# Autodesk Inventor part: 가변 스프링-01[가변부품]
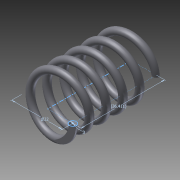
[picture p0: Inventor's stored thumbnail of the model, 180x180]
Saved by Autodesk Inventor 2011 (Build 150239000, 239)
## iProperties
Created: 2015-05
Part Number: 가변 스프링-01[가변부품]
Document SubType Name: Modeling
Designer: Administrator
Density: 7.87 g/cm^3
Mass: 18.9242 g
Surface Area: 32.5548 cm^2
Volume: 2.40459 cm^3
Material: 탄소강
Author: Administrator
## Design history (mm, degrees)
sketch "스케치1"
  geometry: L1 (0, 0)-(11, 0); L2 (11, 0)-(11, 36.411); L3 (11, 36.411)-(0, 36.411); L4 (0, 36.411)-(0, 0); C1 r 1.5 at (11, 0)
  constraints: 8 end point, 2 parallel, 1 centre point, 1 coincident, 1 horizontal, 1 perpendicular
  dimensions: "d0" = 22 diameter of L2 L4; "d1" = 3 diameter of C1; "d2" = 36.4112 distance of L1.end L2.end (derived)
feature "코일1" pitch "d3" = 10; turns "d5" = 5; dims "d4" = 36.4112 (= d2), "d6" = 0, angle "d7" = 90 deg, angle "d8" = 90 deg, "d9" = 0, "d10" = 0
sketch "스케치2"
  geometry: L1 (-12.5, 0)-(-9.5, 0) reference; 1 further point
  constraints: 1 horizontal alignment
extrude "돌출1" cut sketch "스케치2" stored distance "d11" = 10; taper "d12" = 0 deg
node "작업 평면1"
sketch "스케치3"
  geometry: L1 (1.5, 0)-(-1.5, 0) reference; 1 further point
  constraints: 1 horizontal alignment
extrude "돌출2" cut sketch "스케치3" stored distance "d13" = 10; taper "d14" = 0 deg
node "솔리드1"
node "절단 모서리 투영1"
node "절단 모서리 투영2"
